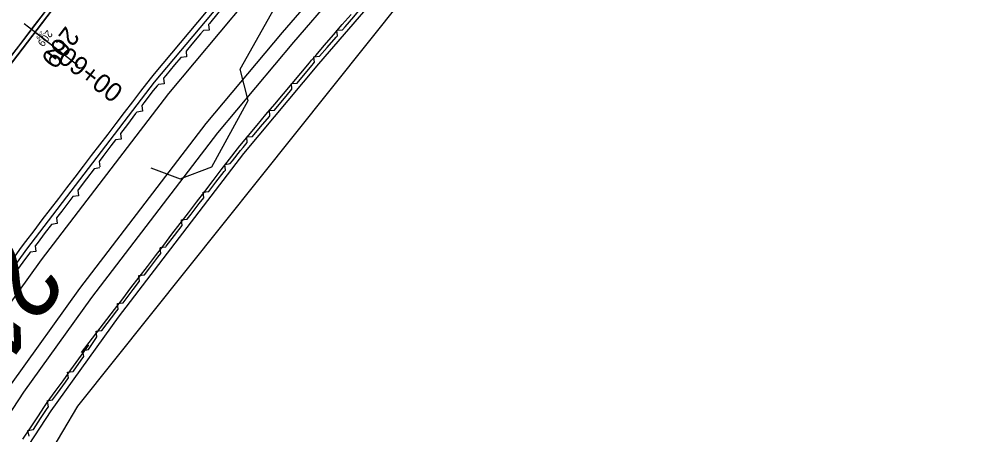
# Model space of a CAD drawing. Extents: x 1823824 to 1861612, y 706975 to 726130.
# Drawn here: x 1824788.8 to 1825141.5, y 711824 to 711977.8 of the extents above; entities that cross this region are included whole.
import ezdxf

# ---------------------------------------------------------------- set-up
doc = ezdxf.new("R2010")
doc.units = 0
for name, color, linetype in [('DR_X_Flood_Boundary', 7, 'Continuous'), ('GE_X_CL_10', 7, 'Continuous'), ('GE_X_CL_100', 7, 'Continuous'), ('GE_X_CL_20', 7, 'Continuous'), ('GE_X_CL_200', 7, 'Continuous'), ('GE_X_CL_50', 7, 'Continuous'), ('RW_X_Esmt_FL', 7, 'Continuous'), ('SC_Scratch1', 7, 'Continuous'), ('SC_Scratch3', 7, 'Continuous'), ('SC_Scratch5', 7, 'Continuous')]:
    doc.layers.add(name, color=color, linetype=linetype)

msp = doc.modelspace()

# ---------------------------------------------------------------- linework, layer by layer
at = {"layer": 'DR_X_Flood_Boundary'}
msp.add_line((1824802.7, 711983.32), (1824754.44, 711920.25), dxfattribs=at)
at = {"layer": 'GE_X_CL_10'}
msp.add_line((1824794.74, 711972.92), (1824795.53, 711972.32), dxfattribs=at)
at = {"layer": 'GE_X_CL_100'}
msp.add_line((1824794.74, 711972.92), (1824802.68, 711966.85), dxfattribs=at)
at = {"layer": 'GE_X_CL_20'}
msp.add_line((1824794.74, 711972.92), (1824796.33, 711971.71), dxfattribs=at)
at = {"layer": 'GE_X_CL_200'}
msp.add_line((1824794.74, 711972.92), (1824810.62, 711960.77), dxfattribs=at)
at = {"layer": 'GE_X_CL_50'}
msp.add_line((1824794.74, 711972.92), (1824798.71, 711969.89), dxfattribs=at)
at = {"layer": 'RW_X_Esmt_FL'}
for p, q in [((1824810.57, 711834.59), (1824941.51, 711998.77)), ((1824689.22, 711630.44), (1824810.57, 711834.59))]:
    msp.add_line(p, q, dxfattribs=at)
at = {"layer": 'SC_Scratch1'}
for p, q in [((1824859.1, 711973.71), (1824857.01, 711973.53)), ((1824858.92, 711975.81), (1824859.1, 711973.71)), ((1824906.37, 711973.68), (1824908.47, 711973.83)), ((1824906.52, 711971.58), (1824906.37, 711973.68)), ((1824850.78, 711963.76), (1824848.68, 711963.57)), ((1824850.59, 711965.86), (1824850.78, 711963.76)), ((1824897.88, 711963.86), (1824899.98, 711964.01)), ((1824898.04, 711961.76), (1824897.88, 711963.86)), ((1824842.27, 711955.9), (1824842.45, 711953.8)), ((1824842.45, 711953.8), (1824840.36, 711953.62)), ((1824889.53, 711953.89), (1824891.63, 711954.08)), ((1824889.72, 711951.8), (1824889.53, 711953.89)), ((1824834.18, 711945.76), (1824834.46, 711943.67)), ((1824834.46, 711943.67), (1824832.37, 711943.39)), ((1824881.21, 711943.94), (1824883.31, 711944.12)), ((1824881.62, 711941.97), (1824881.45, 711944.07)), ((1824826.29, 711935.45), (1824826.57, 711933.36)), ((1824873.04, 711934.18), (1824875.14, 711934.35)), ((1824826.57, 711933.36), (1824824.48, 711933.08)), ((1824873.22, 711932.08), (1824873.04, 711934.18)), ((1824818.41, 711925.14), (1824818.68, 711923.06)), ((1824864.86, 711924.03), (1824866.95, 711924.29)), ((1824865.12, 711921.94), (1824864.86, 711924.03)), ((1824818.71, 711922.72), (1824816.63, 711922.44)), ((1824810.55, 711914.5), (1824810.83, 711912.42)), ((1824856.9, 711913.78), (1824858.99, 711914.05)), ((1824857.16, 711911.7), (1824856.9, 711913.78)), ((1824810.83, 711912.42), (1824808.74, 711912.14)), ((1824802.66, 711904.2), (1824802.94, 711902.11)), ((1824848.93, 711903.54), (1824851.02, 711903.8)), ((1824849.19, 711901.45), (1824848.93, 711903.54)), ((1824802.94, 711902.11), (1824800.85, 711901.83)), ((1824794.78, 711893.89), (1824795.06, 711891.8)), ((1824840.97, 711893.29), (1824843.06, 711893.56)), ((1824841.25, 711891.12), (1824840.98, 711893.2)), ((1824795.06, 711891.8), (1824792.97, 711891.53)), ((1824833.09, 711882.9), (1824835.18, 711883.17)), ((1824833.37, 711880.81), (1824833.09, 711882.9)), ((1824825.21, 711872.59), (1824827.29, 711872.87)), ((1824825.48, 711870.5), (1824825.21, 711872.59)), ((1824817.32, 711862.28), (1824819.41, 711862.56)), ((1824817.6, 711860.2), (1824817.32, 711862.28)), ((1824812.81, 711853.02), (1824812.46, 711855.18)), ((1824812.52, 711855.18), (1824814.53, 711855.51)), ((1824806.74, 711847.12), (1824808.82, 711847.46)), ((1824807.08, 711845.05), (1824806.74, 711847.12)), ((1824799.16, 711836.59), (1824801.24, 711836.93)), ((1824799.67, 711834.32), (1824799.33, 711836.4)), ((1824792.1, 711825.55), (1824794.16, 711825.97)), ((1824792.53, 711823.48), (1824792.1, 711825.55))]:
    msp.add_line(p, q, dxfattribs=at)
for points in [[(1824837.54, 711922.74), (1824848.43, 711918.74), (1824860.1, 711923.16), (1824873.6, 711947.64), (1824870.6, 711959.21), (1824893.22, 711999.63), (1824920.18, 712044.82), (1824961.46, 712108.81), (1824989.89, 712150.42), (1824991.25, 712152.45), (1825003.05, 712154.01), (1825020.13, 712176.93), (1825019.11, 712188.57), (1825068.43, 712250.92), (1825080.52, 712252.77), (1825099.08, 712274.14), (1825098.5, 712286.03), (1825161.91, 712356.25)], [(1824837.54, 711922.74), (1824848.43, 711918.74), (1824860.1, 711923.16), (1824873.6, 711947.64), (1824870.6, 711959.21), (1824893.22, 711999.63), (1824920.18, 712044.82), (1824961.46, 712108.81), (1824989.89, 712150.42), (1824991.25, 712152.45), (1825003.05, 712154.01), (1825020.13, 712176.93), (1825019.11, 712188.57), (1825068.43, 712250.92), (1825080.52, 712252.77), (1825099.08, 712274.14), (1825098.5, 712286.03), (1825161.91, 712356.25)], [(1825105.72, 712238.1), (1825041.58, 712175.28), (1825012.05, 712142.98), (1824928.03, 712058.8), (1824867.42, 711988.62), (1824838.82, 711954.42), (1824791.58, 711892.69), (1824765.73, 711856.76), (1824735.96, 711811.35), (1824706.1, 711762.93), (1824677.47, 711714.29), (1824651.68, 711665.89), (1824630.67, 711625.89), (1824564.54, 711490.46), (1824542.7, 711439.44)], [(1825110.13, 712232.99), (1825046.42, 712170.6), (1825016.92, 712138.33), (1824932.97, 712054.22), (1824872.55, 711984.27), (1824844.08, 711950.22), (1824796.99, 711888.68), (1824771.28, 711852.95), (1824741.64, 711807.74), (1824711.87, 711759.46), (1824683.34, 711710.99), (1824657.63, 711662.75), (1824636.68, 711622.85), (1824570.66, 711487.65), (1824551.08, 711441.92)], [(1825121.76, 712219.53), (1825059.19, 712158.26), (1825029.76, 712126.06), (1824945.98, 712042.13), (1824886.07, 711972.77), (1824857.94, 711939.13), (1824811.24, 711878.1), (1824785.91, 711842.89), (1824756.62, 711798.22), (1824727.07, 711750.3), (1824698.83, 711702.31), (1824673.32, 711654.44), (1824652.51, 711614.83), (1824615.99, 711540.02)], [(1825125.32, 712215.32), (1825063.14, 712154.44), (1825033.74, 712122.26), (1824950.02, 712038.39), (1824890.27, 711969.21), (1824862.23, 711935.69), (1824815.66, 711874.82), (1824790.44, 711839.78), (1824761.26, 711795.26), (1824731.78, 711747.46), (1824703.63, 711699.63), (1824678.18, 711651.87), (1824657.42, 711612.34), (1824626.24, 711548.48)], [(1825133.34, 712206.03), (1825071.96, 712145.93), (1825042.6, 712113.8), (1824959, 712030.04), (1824899.6, 711961.27), (1824871.8, 711928.03), (1824825.5, 711867.52), (1824800.54, 711832.84), (1824771.6, 711788.69), (1824742.28, 711741.14), (1824714.32, 711693.64), (1824689.01, 711646.14), (1824668.35, 711606.81), (1824642.05, 711552.94)], [(1824801.74, 711984.95), (1824801.66, 711984.85), (1824800.75, 711983.67), (1824797.72, 711979.7), (1824794.68, 711975.72), (1824791.64, 711971.75), (1824788.6, 711967.78), (1824785.56, 711963.81), (1824782.53, 711959.84), (1824779.49, 711955.87), (1824776.45, 711951.9), (1824773.41, 711947.93), (1824770.37, 711943.96), (1824767.33, 711939.99), (1824764.3, 711936.01), (1824761.26, 711932.04), (1824758.22, 711928.07), (1824755.18, 711924.1), (1824752.63, 711920.76)], [(1824858, 711980.48), (1824854.8, 711976.65), (1824851.59, 711972.81), (1824848.38, 711968.98), (1824845.17, 711965.14), (1824841.97, 711961.3), (1824838.76, 711957.47), (1824837.26, 711955.68), (1824833.77, 711951.11), (1824830.73, 711947.14), (1824827.69, 711943.17), (1824824.65, 711939.2), (1824821.62, 711935.23), (1824818.58, 711931.26), (1824815.54, 711927.29), (1824812.5, 711923.32), (1824809.46, 711919.34), (1824806.42, 711915.37), (1824803.39, 711911.4), (1824800.35, 711907.43), (1824797.31, 711903.46), (1824794.27, 711899.49), (1824791.23, 711895.52)], [(1824865.33, 711983.48), (1824862.39, 711979.97), (1824859.19, 711976.13), (1824858.92, 711975.81)], [(1824908.47, 711973.83), (1824909.36, 711974.86), (1824912.62, 711978.65), (1824915, 711981.4)], [(1824790.27, 711822.34), (1824793.02, 711826.52), (1824795.76, 711830.7), (1824798.21, 711834.44), (1824799.26, 711835.9), (1824802.18, 711839.96), (1824805.1, 711844.02), (1824808.02, 711848.07), (1824810.94, 711852.13), (1824813.86, 711856.19), (1824814.58, 711857.18), (1824811.95, 711854.47), (1824824.11, 711870.36), (1824827.15, 711874.33), (1824830.19, 711878.3), (1824833.23, 711882.28), (1824836.27, 711886.25), (1824839.3, 711890.22), (1824842.34, 711894.19), (1824845.38, 711898.16), (1824848.42, 711902.13), (1824851.46, 711906.1), (1824854.5, 711910.07), (1824857.53, 711914.04), (1824860.57, 711918.01), (1824863.61, 711921.99), (1824866.65, 711925.96), (1824869.59, 711929.8), (1824870.52, 711930.91), (1824873.73, 711934.75), (1824876.93, 711938.58), (1824880.14, 711942.42), (1824883.35, 711946.25), (1824886.56, 711950.09), (1824889.76, 711953.92), (1824892.97, 711957.76), (1824896.18, 711961.59), (1824896.99, 711962.58), (1824898.53, 711964.36), (1824901.8, 711968.15), (1824905.07, 711971.93), (1824908.33, 711975.72), (1824911.6, 711979.5)], [(1824857.01, 711973.53), (1824855.98, 711972.3), (1824852.77, 711968.46), (1824850.59, 711965.86)], [(1824899.98, 711964.01), (1824902.82, 711967.29), (1824906.09, 711971.08), (1824906.52, 711971.58)], [(1824848.68, 711963.57), (1824846.36, 711960.79), (1824843.15, 711956.96), (1824842.27, 711955.9)], [(1824891.63, 711954.08), (1824893.99, 711956.9), (1824897.2, 711960.74), (1824898.01, 711961.73), (1824898.04, 711961.76)], [(1824840.36, 711953.62), (1824839.94, 711953.12), (1824838.44, 711951.33), (1824834.95, 711946.76), (1824834.18, 711945.76)], [(1824883.31, 711944.12), (1824884.37, 711945.4), (1824887.58, 711949.23), (1824889.72, 711951.8)], [(1824832.37, 711943.39), (1824831.91, 711942.79), (1824828.87, 711938.82), (1824826.29, 711935.45)], [(1824875.14, 711934.35), (1824878.15, 711937.89), (1824881.38, 711941.7), (1824881.62, 711941.97)], [(1824824.48, 711933.08), (1824822.8, 711930.88), (1824819.76, 711926.91), (1824818.41, 711925.14)], [(1824866.95, 711924.29), (1824867.76, 711925.34), (1824870.74, 711929.16), (1824871.67, 711930.26), (1824873.22, 711932.08)], [(1824816.63, 711922.44), (1824813.71, 711918.63), (1824810.67, 711914.66), (1824810.55, 711914.5)], [(1824858.99, 711914.05), (1824861.63, 711917.44), (1824864.69, 711921.39), (1824865.12, 711921.94)], [(1824808.74, 711912.14), (1824807.63, 711910.69), (1824804.6, 711906.72), (1824802.66, 711904.2)], [(1824851.02, 711903.8), (1824852.42, 711905.6), (1824855.49, 711909.55), (1824857.16, 711911.7)], [(1824800.85, 711901.83), (1824798.52, 711898.78), (1824795.48, 711894.81), (1824794.78, 711893.89)], [(1824843.06, 711893.56), (1824843.21, 711893.76), (1824846.28, 711897.71), (1824849.19, 711901.45)], [(1824791.23, 711895.52), (1824789.6, 711893.38), (1824789.03, 711892.56), (1824786.1, 711888.49), (1824783.18, 711884.43), (1824780.26, 711880.37), (1824777.34, 711876.32), (1824774.42, 711872.26), (1824771.5, 711868.2), (1824768.58, 711864.14), (1824765.66, 711860.08), (1824764.08, 711857.89), (1824761.13, 711853.4), (1824758.39, 711849.22), (1824755.65, 711845.04), (1824752.91, 711840.85), (1824750.17, 711836.67), (1824747.43, 711832.49), (1824744.68, 711828.31), (1824741.94, 711824.13), (1824739.2, 711819.95)], [(1824792.97, 711891.53), (1824792.44, 711890.84), (1824790.81, 711888.7), (1824790.24, 711887.88), (1824787.31, 711883.81), (1824787.06, 711883.46)], [(1824835.18, 711883.17), (1824837.14, 711885.74), (1824840.18, 711889.71), (1824841.25, 711891.12)], [(1824827.29, 711872.87), (1824828.03, 711873.83), (1824831.07, 711877.8), (1824833.37, 711880.81)], [(1824819.41, 711862.56), (1824824.99, 711869.86), (1824825.48, 711870.5)], [(1824814.53, 711855.51), (1824817.17, 711859.57), (1824817.61, 711860.25)], [(1824808.82, 711847.46), (1824808.9, 711847.57), (1824811.82, 711851.63), (1824812.81, 711853.02)], [(1824801.24, 711836.93), (1824803.05, 711839.45), (1824805.98, 711843.51), (1824807.08, 711845.05)], [(1824794.16, 711825.97), (1824796.8, 711830), (1824799.25, 711833.74), (1824799.67, 711834.32)]]:
    msp.add_lwpolyline(points, dxfattribs=at)
at = {"layer": 'SC_Scratch3'}
for points in [[(1825072.21, 712272.45), (1825008.3, 712207.43), (1825011.73, 712194.9), (1824990.64, 712173.59), (1824978.07, 712176.88), (1824892.84, 712091.49), (1824830.41, 712019.21), (1824830.77, 712007.17), (1824813.65, 711986.72), (1824801.74, 711984.95), (1824752.63, 711920.76), (1824753.86, 711908.78), (1824738.28, 711887.14), (1824726.53, 711884.51), (1824695.45, 711837.1), (1824665, 711787.73)], [(1824666.49, 711786.8), (1824696.93, 711836.18), (1824727.6, 711882.96), (1824739.31, 711885.58), (1824755.67, 711908.3), (1824754.44, 711920.25), (1824802.7, 711983.32), (1824814.57, 711985.09), (1824832.54, 712006.56), (1824832.18, 712018.58), (1824894.12, 712090.29), (1824978.6, 712174.93), (1824991.17, 712171.64), (1825013.68, 712194.38), (1825010.26, 712206.92), (1825073.72, 712271.49)]]:
    msp.add_lwpolyline(points, dxfattribs=at)
at = {"layer": 'SC_Scratch5'}
msp.add_lwpolyline([(1824798.71, 711969.89), (1824790.77, 711975.96)], dxfattribs=at)

# ---------------------------------------------------------------- texts
at = {"layer": 'GE_X_CL_10'}
msp.add_text('209', height=1.4, rotation=232.5796, dxfattribs=at).set_placement((1824797.02, 711973.44))
at = {"layer": 'GE_X_CL_20'}
msp.add_text('209', height=2.8, rotation=232.5796, dxfattribs=at).set_placement((1824799.31, 711973.95))
at = {"layer": 'GE_X_CL_200'}
msp.add_text('210', height=28, rotation=234.2454, dxfattribs=at).set_placement((1824784.68, 711897.25))
at = {"layer": 'GE_X_CL_50'}
msp.add_text('209', height=7, rotation=232.5796, dxfattribs=at).set_placement((1824806.16, 711975.5))
at = {"layer": 'SC_Scratch5'}
msp.add_text('209+00', height=7, rotation=322.5796, dxfattribs=at).set_placement((1824798.57, 711965.59))

doc.saveas('drawing.dxf')
